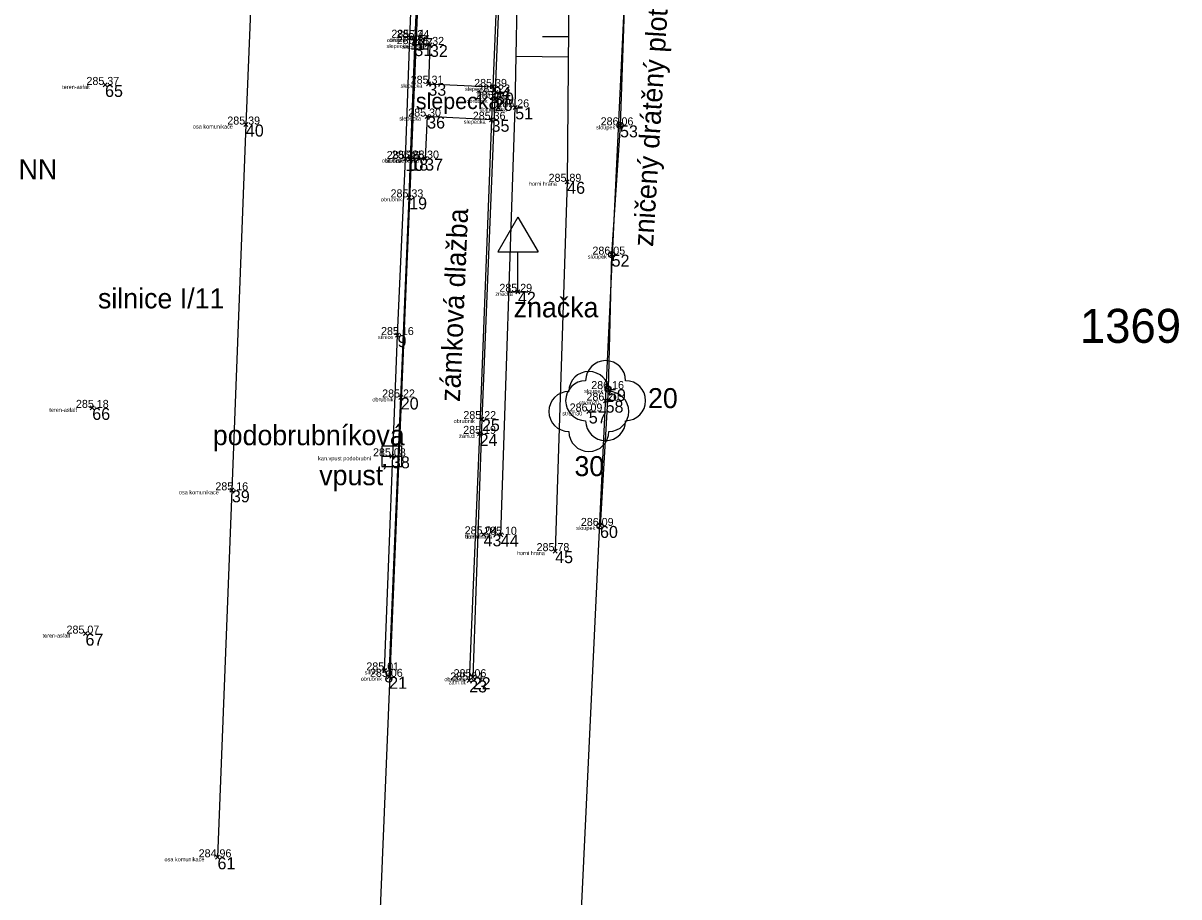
# Model space of a CAD drawing. Extents: x -456675 to -456278, y -1112395 to -1112217.
# Drawn here: x -456558.57 to -456529.68, y -1112322.09 to -1112300.26 of the extents above; entities that cross this region are included whole.
import ezdxf

# ---------------------------------------------------------------- set-up
doc = ezdxf.new("R2010")
doc.units = 0
for name, color, linetype in [('Cislo_bodu', 7, 'Continuous'), ('g_chodniky', 7, 'Continuous'), ('g_dopravni_znaceni', 7, 'Continuous'), ('g_elektrina', 7, 'Continuous'), ('g_kanalizace', 7, 'Continuous'), ('g_komunikace', 7, 'Continuous'), ('g_obrubnik', 7, 'Continuous'), ('g_ploty', 7, 'Continuous'), ('g_terenni_hrany', 7, 'Continuous'), ('g_vegetace', 7, 'Continuous'), ('Katastralni_mapa', 7, 'Continuous'), ('Kod_bodu', 7, 'Continuous'), ('Vyska_bodu', 7, 'Continuous'), ('Znacka_bodu', 7, 'Continuous')]:
    doc.layers.add(name, color=color, linetype=linetype)

msp = doc.modelspace()

# ---------------------------------------------------------------- linework, layer by layer
at = {"layer": 'g_chodniky'}
for points in [[(-456546.28, -1112288.93), (-456546.59, -1112296), (-456546.83, -1112301.85)], [(-456548.776, -1112300.781), (-456548.4, -1112300.8), (-456548.44, -1112301.77), (-456546.83, -1112301.85), (-456546.86, -1112302.67), (-456548.47, -1112302.59), (-456548.52, -1112303.64), (-456548.89, -1112303.64)], [(-456546.86, -1112302.67), (-456547.16, -1112310.52), (-456547.42, -1112316.68)]]:
    msp.add_lwpolyline(points, dxfattribs=at)
at = {"layer": 'g_dopravni_znaceni'}
for p, q in [((-456546.2, -1112305.104), (-456546.7, -1112305.97)), ((-456546.2, -1112305.104), (-456545.7, -1112305.97)), ((-456546.7, -1112305.97), (-456545.7, -1112305.97)), ((-456546.2, -1112306.97), (-456546.2, -1112305.97)), ((-456546.45, -1112306.97), (-456545.95, -1112306.97))]:
    msp.add_line(p, q, dxfattribs=at)
at = {"layer": 'g_kanalizace'}
msp.add_line((-456549.6, -1112311.08), (-456549.1, -1112311.08), dxfattribs=at)
msp.add_lwpolyline([(-456549.6, -1112311.331), (-456549.1, -1112311.331), (-456549.1, -1112310.829), (-456549.6, -1112310.829)], close=True, dxfattribs=at)
at = {"layer": 'g_komunikace'}
for points in [[(-456552.35, -1112286.87), (-456552.57, -1112292.24), (-456553, -1112302.79), (-456553.35, -1112311.93), (-456553.71, -1112321.1)], [(-456549.54, -1112316.43), (-456549.21, -1112308.05), (-456549.01, -1112303.65), (-456548.9, -1112300.62), (-456548.66, -1112294.62), (-456548.46, -1112289.62)]]:
    msp.add_lwpolyline(points, dxfattribs=at)
at = {"layer": 'g_obrubnik'}
for points in [[(-456546.24, -1112289.05), (-456546.54, -1112296.16), (-456546.78, -1112302.15), (-456547.1, -1112310.15), (-456547.33, -1112316.6)], [(-456549.42, -1112316.59), (-456549.13, -1112309.61), (-456548.92, -1112304.61), (-456548.89, -1112303.64), (-456548.77, -1112300.63), (-456548.73, -1112299.65), (-456548.52, -1112294.65), (-456548.32, -1112289.63)]]:
    msp.add_lwpolyline(points, dxfattribs=at)
at = {"layer": 'g_ploty'}
msp.add_lwpolyline([(-456543.11, -1112289.35), (-456543.53, -1112299.42), (-456543.65, -1112302.81), (-456543.86, -1112306.04), (-456543.95, -1112309.4), (-456544.15, -1112312.82)], dxfattribs=at)
for centre in [(-456543.65, -1112302.81), (-456543.86, -1112306.04), (-456543.95, -1112309.4), (-456544.15, -1112312.82)]:
    msp.add_circle(centre, 0.075, dxfattribs=at)
at = {"layer": 'g_terenni_hrany'}
for p, q in [((-456545.588, -1112300.589), (-456544.94, -1112300.594)), ((-456546.245, -1112301.083), (-456544.944, -1112301.094))]:
    msp.add_line(p, q, dxfattribs=at)
for points in [[(-456546.63, -1112313.04), (-456546.27, -1112302.36), (-456546.12, -1112294.59)], [(-456544.89, -1112294.61), (-456544.97, -1112304.22), (-456545.27, -1112313.45)]]:
    msp.add_lwpolyline(points, dxfattribs=at)
at = {"layer": 'g_vegetace'}
for centre in [(-456544.01, -1112309.69), (-456544.43, -1112309.96)]:
    msp.add_circle(centre, 0.0005, dxfattribs=at)
for centre, start, end in [((-456544.01, -1112309.19), 0, 180), ((-456544.43, -1112309.46), 0, 180), ((-456544.51, -1112309.69), 90, 270), ((-456543.51, -1112309.69), 270, 90), ((-456544.93, -1112309.96), 90, 270), ((-456543.93, -1112309.96), 270, 90), ((-456544.01, -1112310.19), 180, 360), ((-456544.43, -1112310.46), 180, 360)]:
    msp.add_arc(centre, 0.5, start, end, dxfattribs=at)
at = {"layer": 'Katastralni_mapa'}
for points in [[(-456546.55, -1112247.69), (-456550.87, -1112351.98)], [(-456545.12, -1112333.16), (-456543.05, -1112289.34)]]:
    msp.add_lwpolyline(points, dxfattribs=at)
at = {"layer": 'Znacka_bodu'}
for p, q in [((-456548.9, -1112300.62), (-456548.95, -1112300.57)), ((-456548.9, -1112300.62), (-456548.95, -1112300.67)), ((-456548.9, -1112300.62), (-456548.85, -1112300.57)), ((-456548.9, -1112300.62), (-456548.85, -1112300.67)), ((-456548.77, -1112300.63), (-456548.82, -1112300.58)), ((-456548.77, -1112300.63), (-456548.82, -1112300.68)), ((-456548.77, -1112300.63), (-456548.72, -1112300.58)), ((-456548.77, -1112300.63), (-456548.72, -1112300.68)), ((-456548.79, -1112300.78), (-456548.84, -1112300.73)), ((-456548.79, -1112300.78), (-456548.84, -1112300.83)), ((-456548.79, -1112300.78), (-456548.74, -1112300.73)), ((-456548.79, -1112300.78), (-456548.74, -1112300.83)), ((-456548.4, -1112300.8), (-456548.45, -1112300.75)), ((-456548.4, -1112300.8), (-456548.45, -1112300.85)), ((-456548.4, -1112300.8), (-456548.35, -1112300.75)), ((-456548.4, -1112300.8), (-456548.35, -1112300.85)), ((-456556.52, -1112301.8), (-456556.57, -1112301.75)), ((-456556.52, -1112301.8), (-456556.57, -1112301.85)), ((-456556.52, -1112301.8), (-456556.47, -1112301.75)), ((-456556.52, -1112301.8), (-456556.47, -1112301.85)), ((-456548.44, -1112301.77), (-456548.49, -1112301.72)), ((-456548.44, -1112301.77), (-456548.49, -1112301.82)), ((-456548.44, -1112301.77), (-456548.39, -1112301.72)), ((-456548.44, -1112301.77), (-456548.39, -1112301.82)), ((-456546.83, -1112301.85), (-456546.88, -1112301.8)), ((-456546.83, -1112301.85), (-456546.88, -1112301.9)), ((-456546.83, -1112301.85), (-456546.78, -1112301.8)), ((-456546.83, -1112301.85), (-456546.78, -1112301.9)), ((-456546.78, -1112302.15), (-456546.83, -1112302.1)), ((-456546.75, -1112301.99), (-456546.8, -1112301.94)), ((-456546.75, -1112301.99), (-456546.8, -1112302.04)), ((-456546.78, -1112302.15), (-456546.73, -1112302.1)), ((-456546.75, -1112301.99), (-456546.7, -1112301.94)), ((-456546.75, -1112301.99), (-456546.7, -1112302.04)), ((-456546.78, -1112302.15), (-456546.83, -1112302.2)), ((-456546.78, -1112302.15), (-456546.73, -1112302.2)), ((-456546.27, -1112302.36), (-456546.32, -1112302.31)), ((-456546.27, -1112302.36), (-456546.32, -1112302.41)), ((-456546.27, -1112302.36), (-456546.22, -1112302.31)), ((-456546.27, -1112302.36), (-456546.22, -1112302.41)), ((-456548.47, -1112302.59), (-456548.52, -1112302.54)), ((-456548.47, -1112302.59), (-456548.52, -1112302.64)), ((-456548.47, -1112302.59), (-456548.42, -1112302.54)), ((-456548.47, -1112302.59), (-456548.42, -1112302.64)), ((-456546.86, -1112302.67), (-456546.91, -1112302.62)), ((-456546.86, -1112302.67), (-456546.91, -1112302.72)), ((-456546.86, -1112302.67), (-456546.81, -1112302.62)), ((-456546.86, -1112302.67), (-456546.81, -1112302.72)), ((-456553, -1112302.79), (-456553.05, -1112302.74)), ((-456553, -1112302.79), (-456553.05, -1112302.84)), ((-456553, -1112302.79), (-456552.95, -1112302.74)), ((-456553, -1112302.79), (-456552.95, -1112302.84)), ((-456543.65, -1112302.81), (-456543.7, -1112302.76)), ((-456543.65, -1112302.81), (-456543.7, -1112302.86)), ((-456543.65, -1112302.81), (-456543.6, -1112302.76)), ((-456543.65, -1112302.81), (-456543.6, -1112302.86)), ((-456549.01, -1112303.65), (-456549.06, -1112303.6)), ((-456549.01, -1112303.65), (-456549.06, -1112303.7)), ((-456549.01, -1112303.65), (-456548.96, -1112303.6)), ((-456549.01, -1112303.65), (-456548.96, -1112303.7)), ((-456548.89, -1112303.64), (-456548.94, -1112303.59)), ((-456548.89, -1112303.64), (-456548.94, -1112303.69)), ((-456548.89, -1112303.64), (-456548.84, -1112303.59)), ((-456548.89, -1112303.64), (-456548.84, -1112303.69)), ((-456548.52, -1112303.64), (-456548.57, -1112303.59)), ((-456548.52, -1112303.64), (-456548.57, -1112303.69)), ((-456548.52, -1112303.64), (-456548.47, -1112303.59)), ((-456548.52, -1112303.64), (-456548.47, -1112303.69)), ((-456544.97, -1112304.22), (-456545.02, -1112304.17)), ((-456544.97, -1112304.22), (-456545.02, -1112304.27)), ((-456544.97, -1112304.22), (-456544.92, -1112304.17)), ((-456544.97, -1112304.22), (-456544.92, -1112304.27)), ((-456548.92, -1112304.61), (-456548.97, -1112304.56)), ((-456548.92, -1112304.61), (-456548.97, -1112304.66)), ((-456548.92, -1112304.61), (-456548.87, -1112304.56)), ((-456548.92, -1112304.61), (-456548.87, -1112304.66)), ((-456543.86, -1112306.04), (-456543.91, -1112305.99)), ((-456543.86, -1112306.04), (-456543.91, -1112306.09)), ((-456543.86, -1112306.04), (-456543.81, -1112305.99)), ((-456543.86, -1112306.04), (-456543.81, -1112306.09)), ((-456546.2, -1112306.97), (-456546.25, -1112306.92)), ((-456546.2, -1112306.97), (-456546.25, -1112307.02)), ((-456546.2, -1112306.97), (-456546.15, -1112306.92)), ((-456546.2, -1112306.97), (-456546.15, -1112307.02)), ((-456549.21, -1112308.05), (-456549.26, -1112308)), ((-456549.21, -1112308.05), (-456549.26, -1112308.1)), ((-456549.21, -1112308.05), (-456549.16, -1112308)), ((-456549.21, -1112308.05), (-456549.16, -1112308.1)), ((-456543.95, -1112309.4), (-456544, -1112309.35)), ((-456543.95, -1112309.4), (-456543.9, -1112309.35)), ((-456549.13, -1112309.61), (-456549.18, -1112309.56)), ((-456549.13, -1112309.61), (-456549.18, -1112309.66)), ((-456549.13, -1112309.61), (-456549.08, -1112309.56)), ((-456549.13, -1112309.61), (-456549.08, -1112309.66)), ((-456544.01, -1112309.69), (-456544.06, -1112309.64)), ((-456544.01, -1112309.69), (-456543.96, -1112309.64)), ((-456543.95, -1112309.4), (-456544, -1112309.45)), ((-456543.95, -1112309.4), (-456543.9, -1112309.45)), ((-456556.84, -1112309.87), (-456556.89, -1112309.82)), ((-456556.84, -1112309.87), (-456556.89, -1112309.92)), ((-456556.84, -1112309.87), (-456556.79, -1112309.82)), ((-456556.84, -1112309.87), (-456556.79, -1112309.92)), ((-456544.43, -1112309.96), (-456544.48, -1112309.91)), ((-456544.43, -1112309.96), (-456544.38, -1112309.91)), ((-456544.01, -1112309.69), (-456544.06, -1112309.74)), ((-456544.01, -1112309.69), (-456543.96, -1112309.74)), ((-456547.1, -1112310.15), (-456547.15, -1112310.1)), ((-456547.1, -1112310.15), (-456547.15, -1112310.2)), ((-456547.1, -1112310.15), (-456547.05, -1112310.1)), ((-456547.1, -1112310.15), (-456547.05, -1112310.2)), ((-456544.43, -1112309.96), (-456544.48, -1112310.01)), ((-456544.43, -1112309.96), (-456544.38, -1112310.01)), ((-456547.16, -1112310.52), (-456547.21, -1112310.47)), ((-456547.16, -1112310.52), (-456547.21, -1112310.57)), ((-456547.16, -1112310.52), (-456547.11, -1112310.47)), ((-456547.16, -1112310.52), (-456547.11, -1112310.57)), ((-456549.35, -1112311.08), (-456549.4, -1112311.03)), ((-456549.35, -1112311.08), (-456549.4, -1112311.13)), ((-456549.35, -1112311.08), (-456549.3, -1112311.03)), ((-456549.35, -1112311.08), (-456549.3, -1112311.13)), ((-456553.35, -1112311.93), (-456553.4, -1112311.88)), ((-456553.35, -1112311.93), (-456553.4, -1112311.98)), ((-456553.35, -1112311.93), (-456553.3, -1112311.88)), ((-456553.35, -1112311.93), (-456553.3, -1112311.98)), ((-456544.15, -1112312.82), (-456544.2, -1112312.77)), ((-456544.15, -1112312.82), (-456544.2, -1112312.87)), ((-456544.15, -1112312.82), (-456544.1, -1112312.77)), ((-456544.15, -1112312.82), (-456544.1, -1112312.87)), ((-456547.06, -1112313.03), (-456547.11, -1112312.98)), ((-456547.06, -1112313.03), (-456547.11, -1112313.08)), ((-456547.06, -1112313.03), (-456547.01, -1112312.98)), ((-456547.06, -1112313.03), (-456547.01, -1112313.08)), ((-456546.63, -1112313.04), (-456546.68, -1112312.99)), ((-456546.63, -1112313.04), (-456546.68, -1112313.09)), ((-456546.63, -1112313.04), (-456546.58, -1112312.99)), ((-456546.63, -1112313.04), (-456546.58, -1112313.09)), ((-456545.27, -1112313.45), (-456545.32, -1112313.4)), ((-456545.27, -1112313.45), (-456545.22, -1112313.4)), ((-456545.27, -1112313.45), (-456545.32, -1112313.5)), ((-456545.27, -1112313.45), (-456545.22, -1112313.5)), ((-456557.01, -1112315.51), (-456557.06, -1112315.46)), ((-456557.01, -1112315.51), (-456557.06, -1112315.56)), ((-456557.01, -1112315.51), (-456556.96, -1112315.46)), ((-456557.01, -1112315.51), (-456556.96, -1112315.56)), ((-456549.54, -1112316.43), (-456549.59, -1112316.38)), ((-456549.54, -1112316.43), (-456549.59, -1112316.48)), ((-456549.54, -1112316.43), (-456549.49, -1112316.38)), ((-456549.54, -1112316.43), (-456549.49, -1112316.48)), ((-456549.42, -1112316.59), (-456549.47, -1112316.54)), ((-456549.42, -1112316.59), (-456549.37, -1112316.54)), ((-456547.33, -1112316.6), (-456547.38, -1112316.55)), ((-456547.33, -1112316.6), (-456547.28, -1112316.55)), ((-456549.42, -1112316.59), (-456549.47, -1112316.64)), ((-456549.42, -1112316.59), (-456549.37, -1112316.64)), ((-456547.42, -1112316.68), (-456547.47, -1112316.63)), ((-456547.42, -1112316.68), (-456547.47, -1112316.73)), ((-456547.42, -1112316.68), (-456547.37, -1112316.63)), ((-456547.42, -1112316.68), (-456547.37, -1112316.73)), ((-456547.33, -1112316.6), (-456547.38, -1112316.65)), ((-456547.33, -1112316.6), (-456547.28, -1112316.65)), ((-456553.71, -1112321.1), (-456553.76, -1112321.05)), ((-456553.71, -1112321.1), (-456553.76, -1112321.15)), ((-456553.71, -1112321.1), (-456553.66, -1112321.05)), ((-456553.71, -1112321.1), (-456553.66, -1112321.15))]:
    msp.add_line(p, q, dxfattribs=at)

# ---------------------------------------------------------------- texts
at = {"layer": 'Cislo_bodu'}
for s, p in [('11', (-456548.9, -1112300.92)), ('17', (-456548.77, -1112300.93)), ('31', (-456548.79, -1112301.08)), ('32', (-456548.4, -1112301.1)), ('65', (-456556.52, -1112302.1)), ('33', (-456548.44, -1112302.07)), ('34', (-456546.83, -1112302.15)), ('50', (-456546.75, -1112302.29)), ('26', (-456546.78, -1112302.45)), ('51', (-456546.27, -1112302.66)), ('36', (-456548.47, -1112302.89)), ('35', (-456546.86, -1112302.97)), ('40', (-456553, -1112303.09)), ('53', (-456543.65, -1112303.11)), ('10', (-456549.01, -1112303.95)), ('18', (-456548.89, -1112303.94)), ('37', (-456548.52, -1112303.94)), ('46', (-456544.97, -1112304.52)), ('19', (-456548.92, -1112304.91)), ('52', (-456543.86, -1112306.34)), ('42', (-456546.2, -1112307.27)), ('9', (-456549.21, -1112308.35)), ('20', (-456549.13, -1112309.91)), ('59', (-456543.95, -1112309.7)), ('66', (-456556.84, -1112310.17)), ('58', (-456544.01, -1112309.99)), ('25', (-456547.1, -1112310.45)), ('57', (-456544.43, -1112310.26)), ('24', (-456547.16, -1112310.82)), ('38', (-456549.35, -1112311.38)), ('39', (-456553.35, -1112312.23)), ('60', (-456544.15, -1112313.12)), ('43', (-456547.06, -1112313.33)), ('44', (-456546.63, -1112313.34)), ('45', (-456545.27, -1112313.75)), ('67', (-456557.01, -1112315.81)), ('8', (-456549.54, -1112316.73)), ('21', (-456549.42, -1112316.89)), ('23', (-456547.42, -1112316.98)), ('22', (-456547.33, -1112316.9)), ('61', (-456553.71, -1112321.4))]:
    msp.add_text(s, height=0.3, dxfattribs=at).set_placement(p)
at = {"layer": 'g_chodniky'}
msp.add_text('slepecká', height=0.4, dxfattribs=at).set_placement((-456548.752, -1112302.403))
msp.add_text('zámková dlažba', height=0.5, rotation=87.5119, dxfattribs=at).set_placement((-456547.653, -1112309.724))
at = {"layer": 'g_dopravni_znaceni'}
msp.add_text('značka', height=0.5, dxfattribs=at).set_placement((-456546.308, -1112307.608))
at = {"layer": 'g_elektrina'}
msp.add_text('dvojitý sloup NN', height=0.5, dxfattribs=at).set_placement((-456562.546, -1112304.158))
at = {"layer": 'g_kanalizace'}
for s, p in [('podobrubníková', (-456553.827, -1112310.802)), ('vpusť', (-456551.167, -1112311.802))]:
    msp.add_text(s, height=0.5, dxfattribs=at).set_placement(p)
at = {"layer": 'g_komunikace'}
msp.add_text('silnice I/11', height=0.5, dxfattribs=at).set_placement((-456556.697, -1112307.384))
at = {"layer": 'g_ploty'}
msp.add_text('zničený drátěný plot', height=0.5, rotation=86.4834, dxfattribs=at).set_placement((-456542.825, -1112305.852))
at = {"layer": 'g_vegetace'}
for s, p in [('20', (-456542.951, -1112309.876)), ('30', (-456544.789, -1112311.575))]:
    msp.add_text(s, height=0.5, dxfattribs=at).set_placement(p)
at = {"layer": 'Katastralni_mapa'}
msp.add_text('1369', height=0.85, dxfattribs=at).set_placement((-456532.157, -1112308.245))
at = {"layer": 'Kod_bodu'}
for s, p in [('obrubnik', (-456549.48, -1112300.73)), ('silnice', (-456549.391, -1112300.72)), ('slepecka', (-456549.485, -1112300.88)), ('slepecka', (-456549.095, -1112300.9)), ('teren-asfalt', (-456557.593, -1112301.9)), ('slepecka', (-456549.135, -1112301.87)), ('slepecka', (-456547.525, -1112301.95)), ('teren', (-456547.215, -1112302.09)), ('obrubnik', (-456547.49, -1112302.25)), ('dolni hrana', (-456547.161, -1112302.46)), ('slepecka', (-456549.165, -1112302.69)), ('slepecka', (-456547.555, -1112302.77)), ('osa komunikace', (-456554.325, -1112302.89)), ('sloupek', (-456544.245, -1112302.91)), ('obrubnik', (-456549.6, -1112303.74)), ('silnice', (-456549.501, -1112303.75)), ('slepecka', (-456549.215, -1112303.74)), ('horni hrana', (-456545.926, -1112304.32)), ('obrubnik', (-456549.63, -1112304.71)), ('sloupek', (-456544.455, -1112306.14)), ('znacka', (-456546.767, -1112307.07)), ('silnice', (-456549.701, -1112308.15)), ('obrubnik', (-456549.84, -1112309.71)), ('sloupek', (-456544.545, -1112309.5)), ('teren-asfalt', (-456557.913, -1112309.97)), ('strom20', (-456544.673, -1112309.79)), ('obrubnik', (-456547.81, -1112310.25)), ('strom30', (-456545.093, -1112310.06)), ('zam.dl.', (-456547.672, -1112310.62)), ('kan.vpust podobrubni', (-456551.196, -1112311.18)), ('osa komunikace', (-456554.675, -1112312.03)), ('sloupek', (-456544.745, -1112312.92)), ('teren', (-456547.525, -1112313.13)), ('dolni hrana', (-456547.521, -1112313.14)), ('horni hrana', (-456546.226, -1112313.55)), ('teren-asfalt', (-456558.083, -1112315.61)), ('obrubnik', (-456550.13, -1112316.69)), ('silnice', (-456550.031, -1112316.53)), ('obrubnik', (-456548.04, -1112316.7)), ('zam.dl.', (-456547.932, -1112316.78)), ('osa komunikace', (-456555.035, -1112321.2))]:
    msp.add_text(s, height=0.1, dxfattribs=at).set_placement(p)
at = {"layer": 'Vyska_bodu'}
for s, p in [('285.34', (-456549.365, -1112300.62)), ('285.34', (-456549.235, -1112300.63)), ('285.31', (-456549.231, -1112300.78)), ('285.32', (-456548.865, -1112300.8)), ('285.37', (-456556.985, -1112301.8)), ('285.31', (-456548.881, -1112301.77)), ('285.39', (-456547.295, -1112301.85)), ('285.23', (-456547.215, -1112301.99)), ('285.40', (-456547.253, -1112302.15)), ('285.30', (-456548.943, -1112302.59)), ('285.26', (-456546.74, -1112302.36)), ('285.39', (-456553.465, -1112302.79)), ('285.36', (-456547.33, -1112302.67)), ('286.06', (-456544.134, -1112302.81)), ('285.26', (-456549.48, -1112303.65)), ('285.28', (-456549.355, -1112303.64)), ('285.30', (-456548.993, -1112303.64)), ('285.89', (-456545.435, -1112304.22)), ('285.33', (-456549.385, -1112304.61)), ('286.05', (-456544.339, -1112306.04)), ('285.29', (-456546.665, -1112306.97)), ('285.16', (-456549.623, -1112308.05)), ('286.16', (-456544.369, -1112309.4)), ('285.22', (-456549.595, -1112309.61)), ('286.20', (-456544.489, -1112309.69)), ('285.18', (-456557.248, -1112309.87)), ('286.09', (-456544.909, -1112309.96)), ('285.22', (-456547.565, -1112310.15)), ('285.19', (-456547.569, -1112310.52)), ('285.08', (-456549.823, -1112311.08)), ('285.16', (-456553.763, -1112311.93)), ('285.04', (-456547.533, -1112313.03)), ('286.09', (-456544.629, -1112312.82)), ('285.10', (-456547.047, -1112313.04)), ('285.78', (-456545.735, -1112313.45)), ('285.07', (-456557.483, -1112315.51)), ('285.01', (-456549.99, -1112316.43)), ('285.06', (-456549.899, -1112316.59)), ('285.04', (-456547.893, -1112316.68)), ('285.06', (-456547.809, -1112316.6)), ('284.96', (-456554.181, -1112321.1))]:
    msp.add_text(s, height=0.2, dxfattribs=at).set_placement(p)

doc.saveas('drawing.dxf')
